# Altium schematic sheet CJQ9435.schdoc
size 127 x 101 mm
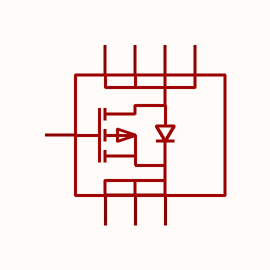
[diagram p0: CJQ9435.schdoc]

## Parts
Q?  cjq9435  [SOP-8_L5.0-W4.0-P1.27-LS6.2-BL]  (value not drawn)

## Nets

Not connected (* = marked no-connect by the designer): Q? 1(S) 2(S) 3(S) 4(G) 5(D) 6(D) 7(D) 8(D)

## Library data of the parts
Q? = cjq9435: 数量:1个P沟道;漏源电压(Vdss):30V;连续漏极电流(Id):5.1A;导通电阻(RDS(on)):105mΩ@4.5V;耗散功率(Pd):1.4W;阈值电压(Vgs(th)):2V;; Manufacturer: CJ(江苏长电/长晶); AddInBom: yes; ModelId: a3315c1c78f949e6bb82c6eaca1c53c7; ModelName: SOP-8_L5.0-W4.0-H1.8-LS6.2-P1.27; ModelTransform: 244.094,196.85,0,90,0,0,0,0,0; Number: 1个P沟道; Drain to Source Voltage: 30V; Current - Continuous Drain(Id): 5.1A; Pd - Power Dissipation: 1.4W; Gate Threshold Voltage (Vgs(th)): 2V; Gate Charge(Qg): 40nC@10V; Type: P沟道; Vgs: ±20V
